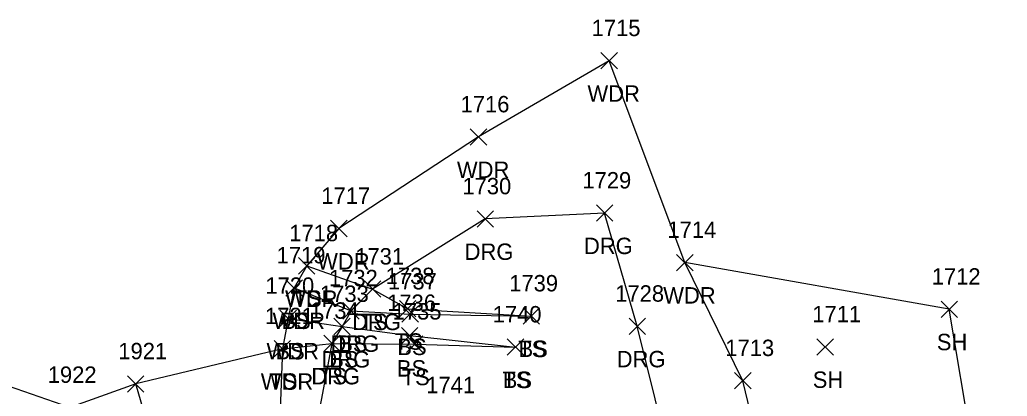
# Model space of a CAD drawing. Extents: x 1600281 to 1602254, y 862855 to 863227.
# Drawn here: x 1601993.2 to 1602113.6, y 863181.1 to 863227 of the extents above; entities that cross this region are included whole.
import ezdxf

# ---------------------------------------------------------------- set-up
doc = ezdxf.new("R2010")
doc.units = 0
for name, color, linetype in [('L_A', 7, 'Continuous'), ('L_I', 7, 'Continuous'), ('L_TIC', 7, 'Continuous'), ('LAWA', 7, 'Continuous'), ('LELB', 7, 'Continuous'), ('LSOGP', 7, 'Continuous'), ('R_A', 7, 'Continuous'), ('R_I', 7, 'Continuous'), ('R_TIC', 7, 'Continuous'), ('RDG', 7, 'Continuous')]:
    doc.layers.add(name, color=color, linetype=linetype)

msp = doc.modelspace()

# ---------------------------------------------------------------- linework, layer by layer
at = {"layer": 'L_TIC'}
for points in [[(1602064.05, 863221), (1602066.05, 863223)], [(1602066.05, 863221), (1602064.05, 863223)], [(1602048.13, 863211.71), (1602050.13, 863213.71)], [(1602050.13, 863211.71), (1602048.13, 863213.71)], [(1602031.11, 863200.55), (1602033.11, 863202.55)], [(1602033.11, 863200.55), (1602031.11, 863202.55)], [(1602027.2, 863196), (1602029.2, 863198)], [(1602029.2, 863196), (1602027.2, 863198)], [(1602027.2, 863196), (1602029.2, 863198)], [(1602029.2, 863196), (1602027.2, 863198)], [(1602073.27, 863196.4), (1602075.27, 863198.4)], [(1602075.27, 863196.4), (1602073.27, 863198.4)], [(1602025.67, 863193.3), (1602027.67, 863195.3)], [(1602027.67, 863193.3), (1602025.67, 863195.3)], [(1602025.67, 863193.3), (1602027.67, 863195.3)], [(1602027.67, 863193.3), (1602025.67, 863195.3)], [(1602035.23, 863193.16), (1602037.23, 863195.16)], [(1602037.23, 863193.16), (1602035.23, 863195.16)], [(1602039.51, 863190.77), (1602041.51, 863192.77)], [(1602041.51, 863190.77), (1602039.51, 863192.77)], [(1602105.49, 863190.71), (1602107.49, 863192.71)], [(1602107.49, 863190.71), (1602105.49, 863192.71)], [(1602024.94, 863189.59), (1602026.94, 863191.59)], [(1602026.94, 863189.59), (1602024.94, 863191.59)], [(1602024.94, 863189.59), (1602026.94, 863191.59)], [(1602026.94, 863189.59), (1602024.94, 863191.59)], [(1602032.6, 863190.51), (1602034.6, 863192.51)], [(1602034.6, 863190.51), (1602032.6, 863192.51)], [(1602039.8, 863190.12), (1602041.8, 863192.12)], [(1602041.8, 863190.12), (1602039.8, 863192.12)], [(1602054.57, 863189.88), (1602056.57, 863191.88)], [(1602056.57, 863189.88), (1602054.57, 863191.88)], [(1602054.57, 863189.88), (1602056.57, 863191.88)], [(1602056.57, 863189.88), (1602054.57, 863191.88)], [(1602031.5, 863188.6), (1602033.5, 863190.6)], [(1602033.5, 863188.6), (1602031.5, 863190.6)], [(1602039.75, 863187.5), (1602041.75, 863189.5)], [(1602041.75, 863187.5), (1602039.75, 863189.5)], [(1602024.23, 863185.89), (1602026.23, 863187.89)], [(1602026.23, 863185.89), (1602024.23, 863187.89)], [(1602024.23, 863185.89), (1602026.23, 863187.89)], [(1602026.23, 863185.89), (1602024.23, 863187.89)], [(1602030.27, 863186.55), (1602032.27, 863188.55)], [(1602032.27, 863186.55), (1602030.27, 863188.55)], [(1602040.36, 863186.45), (1602042.36, 863188.45)], [(1602042.36, 863186.45), (1602040.36, 863188.45)], [(1602052.64, 863186.1), (1602054.64, 863188.1)], [(1602054.64, 863186.1), (1602052.64, 863188.1)], [(1602052.64, 863186.1), (1602054.64, 863188.1)], [(1602054.64, 863186.1), (1602052.64, 863188.1)], [(1602090.37, 863186.12), (1602092.37, 863188.12)], [(1602092.37, 863186.12), (1602090.37, 863188.12)], [(1602006.36, 863181.61), (1602008.36, 863183.61)], [(1602008.36, 863181.61), (1602006.36, 863183.61)], [(1602080.34, 863182), (1602082.34, 863184)], [(1602082.34, 863182), (1602080.34, 863184)]]:
    msp.add_lwpolyline(points, dxfattribs=at)
at = {"layer": 'LAWA'}
msp.add_lwpolyline([(1602117.19, 863138.12), (1602108.93, 863139.2), (1602098.44, 863147.47), (1602087.13, 863158.97), (1602081.34, 863183), (1602074.27, 863197.4), (1602065.05, 863222), (1602049.13, 863212.71), (1602032.11, 863201.55), (1602028.2, 863197), (1602026.67, 863194.3), (1602025.94, 863190.59), (1602025.23, 863186.89), (1602024.69, 863172.02), (1602032.79, 863158.74), (1602049.66, 863136.08), (1602061.61, 863128.63), (1602064.82, 863129.78), (1602064.98, 863118.42), (1602058.16, 863113.92), (1602052.16, 863106.95), (1602042.21, 863103.01), (1602035.27, 863100.33)], dxfattribs=at)
at = {"layer": 'LELB'}
for points in [[(1602028.2, 863197), (1602036.23, 863194.16), (1602040.51, 863191.77), (1602055.57, 863190.88)], [(1602026.67, 863194.3), (1602033.6, 863191.51), (1602040.8, 863191.12), (1602055.57, 863190.88)], [(1602025.94, 863190.59), (1602032.5, 863189.6), (1602040.75, 863188.5), (1602053.64, 863187.1)], [(1602025.23, 863186.89), (1602031.27, 863187.55), (1602041.36, 863187.45), (1602053.64, 863187.1)], [(1602012.72, 863164.16), (1602007.36, 863182.61), (1601999.34, 863179.73), (1602001.22, 863160.85), (1602009.64, 863146)]]:
    msp.add_lwpolyline(points, dxfattribs=at)
at = {"layer": 'LSOGP'}
msp.add_lwpolyline([(1602125.54, 863173.4), (1602109.27, 863175.06), (1602106.49, 863191.71), (1602074.27, 863197.4), (1602065.05, 863222), (1602049.13, 863212.71), (1602032.11, 863201.55), (1602028.2, 863197), (1602026.67, 863194.3), (1602025.94, 863190.59), (1602025.23, 863186.89), (1602007.36, 863182.61), (1601999.34, 863179.73), (1601966.6, 863191.09), (1601957.22, 863184.57), (1601933.61, 863167.48), (1601930.07, 863156.54), (1601924.03, 863153.21)], dxfattribs=at)
at = {"layer": 'R_TIC'}
for points in [[(1602048.95, 863201.72), (1602050.95, 863203.72)], [(1602050.95, 863201.72), (1602048.95, 863203.72)], [(1602063.5, 863202.43), (1602065.5, 863204.43)], [(1602065.5, 863202.43), (1602063.5, 863204.43)], [(1602035.23, 863193.16), (1602037.23, 863195.16)], [(1602037.23, 863193.16), (1602035.23, 863195.16)], [(1602032.6, 863190.51), (1602034.6, 863192.51)], [(1602034.6, 863190.51), (1602032.6, 863192.51)], [(1602031.5, 863188.6), (1602033.5, 863190.6)], [(1602033.5, 863188.6), (1602031.5, 863190.6)], [(1602067.48, 863188.63), (1602069.48, 863190.63)], [(1602069.48, 863188.63), (1602067.48, 863190.63)], [(1602030.27, 863186.55), (1602032.27, 863188.55)], [(1602032.27, 863186.55), (1602030.27, 863188.55)]]:
    msp.add_lwpolyline(points, dxfattribs=at)
at = {"layer": 'RDG'}
msp.add_lwpolyline([(1602096.31, 863123.24), (1602095.85, 863125.02), (1602094.92, 863127.7), (1602091.39, 863132.44), (1602080.77, 863146.09), (1602073.92, 863167.68), (1602068.48, 863189.63), (1602064.5, 863203.43), (1602049.95, 863202.72), (1602036.23, 863194.16), (1602033.6, 863191.51), (1602032.5, 863189.6), (1602031.27, 863187.55), (1602028.66, 863173.71), (1602035.78, 863160.03), (1602055.15, 863139.43), (1602064.82, 863129.78), (1602067.69, 863122.35), (1602069.71, 863119.92), (1602071.56, 863117.44), (1602075.42, 863112.31)], dxfattribs=at)

# ---------------------------------------------------------------- texts
at = {"layer": 'L_A'}
for s, p in [('WDR', (1602062.41, 863217)), ('WDR', (1602046.5, 863207.71)), ('WDR', (1602029.47, 863196.55)), ('WDR', (1602025.56, 863192)), ('TS', (1602026.61, 863192)), ('WDR', (1602071.64, 863192.4)), ('WDR', (1602024.03, 863189.3)), ('BS', (1602025.11, 863189.3)), ('TS', (1602034.64, 863189.16)), ('BS', (1602032.04, 863186.51)), ('TS', (1602038.92, 863186.77)), ('BS', (1602039.24, 863186.12)), ('TS', (1602053.98, 863185.88)), ('BS', (1602054.01, 863185.88)), ('SH', (1602104.98, 863186.71)), ('WDR', (1602023.3, 863185.59)), ('BS', (1602024.38, 863185.59)), ('BS', (1602030.94, 863184.6)), ('BS', (1602039.19, 863183.5)), ('TS', (1602029.68, 863182.55)), ('TS', (1602039.77, 863182.45)), ('WDR', (1602022.6, 863181.89)), ('TS', (1602023.64, 863181.89)), ('TS', (1602052.05, 863182.1)), ('BS', (1602052.08, 863182.1)), ('SH', (1602089.86, 863182.12))]:
    msp.add_text(s, height=2, dxfattribs=at).set_placement(p)
at = {"layer": 'L_I'}
for s, p in [('1715', (1602062.92, 863225)), ('1716', (1602046.95, 863215.71)), ('1717', (1602029.98, 863204.55)), ('1714', (1602072.15, 863200.4)), ('1718', (1602026.07, 863200)), ('1718', (1602026.07, 863200)), ('1719', (1602024.53, 863197.3)), ('1719', (1602024.53, 863197.3)), ('1731', (1602034.11, 863197.16)), ('1732', (1602030.91, 863194.51)), ('1738', (1602037.82, 863194.77)), ('1712', (1602104.36, 863194.71)), ('1720', (1602023.16, 863193.59)), ('1720', (1602023.16, 863193.59)), ('1737', (1602038.1, 863194.12)), ('1739', (1602052.87, 863193.88)), ('1739', (1602052.87, 863193.88)), ('1733', (1602029.81, 863192.6)), ('1736', (1602038, 863191.5)), ('1721', (1602023.11, 863189.89)), ('1721', (1602023.11, 863189.89)), ('1734', (1602028.58, 863190.55)), ('1735', (1602038.67, 863190.45)), ('1740', (1602050.86, 863190.1)), ('1740', (1602050.86, 863190.1)), ('1711', (1602089.81, 863190.12)), ('1713', (1602079.21, 863186)), ('1921', (1602005.24, 863185.61)), ('1922', (1601996.64, 863182.73)), ('1741', (1602042.76, 863181.47))]:
    msp.add_text(s, height=2, dxfattribs=at).set_placement(p)
at = {"layer": 'R_A'}
for p in [(1602061.98, 863198.43), (1602047.44, 863197.72), (1602033.72, 863189.16), (1602031.09, 863186.51), (1602029.99, 863184.6), (1602065.97, 863184.63), (1602028.76, 863182.55)]:
    msp.add_text('DRG', height=2, dxfattribs=at).set_placement(p)
at = {"layer": 'R_I'}
for s, p in [('1729', (1602061.79, 863206.43)), ('1730', (1602047.17, 863205.72)), ('1731', (1602034.11, 863197.16)), ('1732', (1602030.91, 863194.51)), ('1733', (1602029.81, 863192.6)), ('1728', (1602065.79, 863192.63)), ('1734', (1602028.58, 863190.55))]:
    msp.add_text(s, height=2, dxfattribs=at).set_placement(p)

doc.saveas('drawing.dxf')
